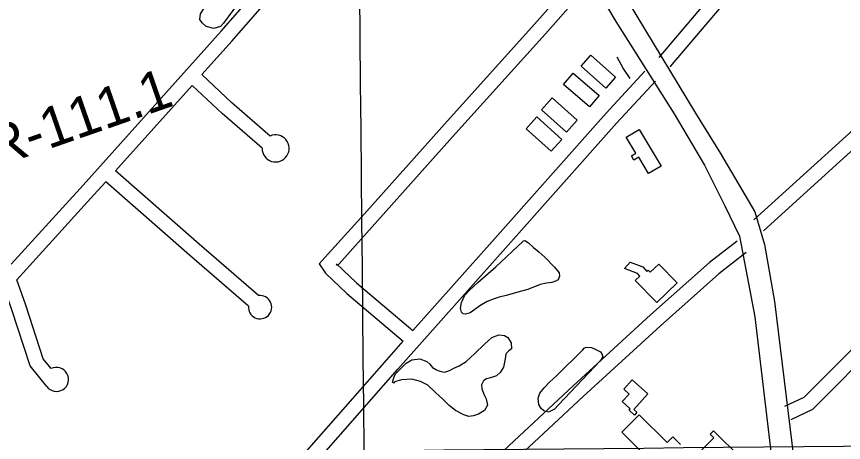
# Model space of a CAD drawing. Extents: x 3625074 to 3663148, y 511451 to 537151.
# Drawn here: x 3633748 to 3635455, y 529050 to 529928 of the extents above; entities that cross this region are included whole.
import ezdxf

# ---------------------------------------------------------------- set-up
doc = ezdxf.new("R2010")
doc.units = 0
for name, color, linetype in [('V-BLDG-OTLN', 7, 'Continuous'), ('V-GRID-MAJR', 7, 'Continuous'), ('V-RIVR-RANG-IDEN', 7, 'Continuous'), ('V-ROAD-CNTR', 7, 'Continuous'), ('V-SITE-VEGE', 7, 'Continuous'), ('V-SURV-IDEN', 7, 'Continuous'), ('V-TOPO-SHOR', 7, 'Continuous')]:
    doc.layers.add(name, color=color, linetype=linetype)

msp = doc.modelspace()

# ---------------------------------------------------------------- linework, layer by layer
at = {"layer": 'V-BLDG-OTLN'}
for points in [[(3634933.9560000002, 529848.573), (3634984.804, 529803.001), (3634964.6780000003, 529780.547), (3634913.83, 529826.1190000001)], [(3634930.827, 529742.05), (3634877.239, 529788.45), (3634897.469, 529811.8150000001), (3634951.057, 529765.416)], [(3634883.665, 529690.047), (3634832.037, 529736.023), (3634853.848, 529760.517), (3634905.4790000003, 529714.542)], [(3634852.022, 529650.398), (3634800.004, 529696.773), (3634821.867, 529721.296), (3634873.88, 529674.917)], [(3635033.1750000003, 529695.335), (3635078.8680000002, 529619.953), (3635053.0470000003, 529604.302), (3635032.532, 529638.143), (3635022.714, 529632.194), (3635017.3910000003, 529640.973), (3635026.5870000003, 529646.5480000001), (3635006.73, 529679.306)], [(3635111.9250000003, 529379.204), (3635070.037, 529338.133), (3635025.504, 529383.554), (3635035.049, 529392.9130000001), (3635030.021, 529398.49), (3635003.037, 529408.716), (3635014.629, 529421.522), (3635041.224, 529411.696), (3635049.348, 529402.531), (3635052.275, 529405.13), (3635055.88, 529401.066), (3635074.4220000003, 529417.455)], [(3634998.632, 529133.907), (3635012.622, 529149.433), (3635001.687, 529159.284), (3635019.12, 529178.629), (3635051.315, 529149.617), (3635022.495, 529117.638), (3635028.9050000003, 529111.862), (3635023.603, 529105.978), (3635012.532, 529115.958), (3635015.227, 529118.954)]]:
    msp.add_lwpolyline(points, close=True, dxfattribs=at)
for points in [[(3635038.562, 529030.131), (3634997.589, 529070.513), (3635033.45, 529106.898), (3635091.572, 529049.613), (3635102.846, 529061.053), (3635118.864, 529045.267)], [(3635135.852, 529006.72), (3635187.5500000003, 529059.1730000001), (3635180.042, 529066.575), (3635186.921, 529073.554), (3635244.406, 529016.8960000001)]]:
    msp.add_lwpolyline(points, dxfattribs=at)
at = {"layer": 'V-GRID-MAJR'}
for points in [[(3634583.656, 516913.037), (3634524.612, 522971.789), (3634465.549, 529032.474), (3634406.486, 535093.172), (3634406.467, 535095.091)], [(3629187.62, 528981.4230000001), (3634465.549, 529032.474), (3639743.471, 529084.2930000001), (3645021.3850000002, 529136.879)]]:
    msp.add_spline(points, degree=3, dxfattribs=at)
at = {"layer": 'V-ROAD-CNTR'}
for points in [[(3633673.938, 532162.153), (3633780.89, 531985.916), (3633876.6, 531828.509), (3633996.825, 531630.389), (3634264.9990000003, 531191.1460000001), (3634381.197, 530998.172), (3634645.052, 530565.506), (3634778.911, 530342.151), (3635026.809, 529932.475), (3635149.623, 529729.158), (3635201.133, 529645.657), (3635237.929, 529583.988), (3635272.433, 529525.164), (3635292.1520000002, 529457.799), (3635312.892, 529340.52), (3635368.435, 528885.332), (3635402.846, 528578.8960000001), (3635468.14, 527984.167), (3635498.877, 527720.385)], [(3633679.897, 532075.356), (3633969.983, 531601.076), (3634194.6240000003, 531230.475), (3634340.754, 530986.403), (3634517.023, 530698.934), (3634735.024, 530339.394), (3634985.259, 529918.023), (3635105.444, 529727.834), (3635168.1010000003, 529621.4130000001), (3635210.481, 529537.829), (3635240.924, 529474.947), (3635272.682, 529308.5700000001), (3635319.328, 528914.598), (3635361.137, 528548.576), (3635414.789, 528072.17), (3635474.574, 527551.515)], [(3633736.983, 529417.275), (3633885.366, 529580.647), (3634170.376, 529898.301), (3634411.054, 530173.101), (3634609.2, 530397.257), (3634634.475, 530427.709), (3634669.275, 530458.221)], [(3634130.2800000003, 529808.691), (3634192.826, 529878.401), (3634433.576, 530153.283), (3634631.986, 530377.737), (3634656.041, 530406.719), (3634676.843, 530424.959)], [(3635097.576, 529824.55), (3635282.205, 530042.104), (3635443.794, 530224.98)], [(3635074.702, 529843.962), (3635259.525, 530061.7440000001), (3635337.7830000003, 530150.311)], [(3634916.355, 530024.9720000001), (3634817.649, 529912.602), (3634625.97, 529700.118), (3634465.501, 529520.884), (3634391.5530000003, 529438.5160000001), (3634372.912, 529418.077), (3634385.518, 529398.6630000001), (3634429.657, 529356.58), (3634546.188, 529258.274)], [(3634938.895, 530005.174), (3634840.057, 529892.654), (3634648.284, 529680.066), (3634487.839, 529500.858), (3634413.799, 529418.388), (3634410.6920000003, 529414.981), (3634408.764, 529417.949), (3634449.699, 529378.922), (3634566.16, 529280.675)], [(3635270.429, 529508.681), (3635585.307, 529794.431), (3635751.312, 529950.38)], [(3635290.589, 529486.465), (3635605.659, 529772.389), (3635739.305, 529897.9400000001)], [(3634566.16, 529280.674), (3634729.704, 529464.107), (3634965.34, 529729.268), (3635045.515, 529815.501)], [(3633810.1350000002, 529165.0700000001), (3633775.994, 529207.667), (3633738.269, 529322.968), (3633699.028, 529434.85), (3633629.878, 529629.93), (3633592.8140000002, 529733.631), (3633587.857, 529753.635), (3633584.154, 529798.039)], [(3634271.469, 529681.875), (3634192.36, 529750.497), (3634130.2800000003, 529808.691)], [(3633912.299, 528497.0650000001), (3634024.046, 528624.74), (3634254.102, 528881.164), (3634534.839, 529200.464), (3634752.112, 529444.161), (3634987.54, 529709.088), (3635067.485, 529795.073)], [(3633951.913, 529609.895), (3634110.24, 529786.356)], [(3634254.813, 529656.609), (3634172.2660000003, 529728.215), (3634110.241, 529786.355)], [(3635334.545, 529124.263), (3635374.307, 529142.9890000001), (3635510.6780000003, 529279.305), (3635826.258, 529611.095), (3635924.861, 529720.085)], [(3635347.327, 529097.123), (3635391.819, 529118.075), (3635532.154, 529258.355), (3635848.254, 529590.691), (3635946.595, 529699.3910000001)], [(3634247.738, 529352.502), (3634124.87, 529458.427), (3633951.914, 529609.895)], [(3633748.273, 529385.085), (3633907.634, 529560.545), (3633931.877, 529587.564)], [(3634226.744, 529330.992), (3634105.1920000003, 529435.781), (3633931.878, 529587.564)], [(3635235.9250000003, 529465.003), (3635178.539, 529420.721), (3635057.132, 529312.661), (3634897.5530000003, 529166.2980000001), (3634754.852, 529033.805), (3634624.396, 528911.731), (3634488.5840000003, 528777.251)], [(3635254.253, 529441.251), (3635197.699, 529397.613), (3635077.244, 529290.401), (3634917.899, 529144.25), (3634775.308, 529011.859), (3634645.204, 528890.115), (3634530.733, 528776.77)], [(3633819.106, 529201.8470000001), (3633802.812, 529222.177), (3633766.683, 529332.598), (3633748.274, 529385.085)], [(3634025.85, 528671.675), (3634231.6720000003, 528901.086), (3634512.377, 529220.35), (3634546.188, 529258.273)]]:
    msp.add_lwpolyline(points, dxfattribs=at)
for centre, radius, start, end in [((3634282.768383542, 529656.3027480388), 27.95717053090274, 179.37302008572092, 113.83899508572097), ((3634250.670490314, 529328.6388426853), 24.042239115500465, 174.38260938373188, 97.0053927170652), ((3633830.337554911, 529179.6248104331), 24.899164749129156, 215.77029654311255, 116.81182432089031)]:
    msp.add_arc(centre, radius, start, end, dxfattribs=at)
at = {"layer": 'V-SITE-VEGE'}
for points in [[(3634142.2770000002, 530096.686), (3634141.742, 530100.202), (3634141.761, 530101.372), (3634143.582, 530106.023), (3634145.953, 530108.327), (3634157.61, 530105.816), (3634225.7490000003, 530047.526), (3634247.077, 530026.751), (3634249.863, 530017.357), (3634175.287, 529914.961), (3634168.756, 529908.041), (3634155.245, 529903.562), (3634139.518, 529907.883), (3634130.861, 529915.61), (3634126.2800000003, 529922.108), (3634127.619, 529933.782), (3634146.176, 529963.328), (3634194.384, 530021.674), (3634203.418, 530039.6680000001), (3634201.792, 530048.46), (3634196.608, 530053.799)], [(3634792.953, 529464.276), (3634794.725, 529465.419), (3634797.6550000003, 529465.961), (3634805.194, 529461.759), (3634814.988, 529451.675), (3634826.549, 529442.737), (3634838.673, 529432.036), (3634858.8310000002, 529411.28), (3634868.012, 529399.453), (3634869.079, 529392.424), (3634866.055, 529385.448), (3634860.75, 529382.604), (3634853.109, 529379.792), (3634841.9760000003, 529378.201), (3634829.076, 529375.464), (3634803.785, 529365.31), (3634790.2830000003, 529361.415), (3634758.59, 529353.108), (3634744.502, 529349.221), (3634733.9280000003, 529345.8690000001), (3634719.815, 529340.227), (3634704.49, 529331.68), (3634693.846, 529323.652), (3634684.393, 529316.775), (3634674.997, 529313.988), (3634670.329, 529314.6410000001), (3634666.876, 529318.198), (3634664.654, 529326.417), (3634666.5870000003, 529338.666), (3634673.239, 529353.77), (3634683.322, 529363.561), (3634700.515, 529379.681), (3634737.231, 529411.886)], [(3634528.552, 529174.64), (3634527.926, 529171.725), (3634523.858, 529173.542), (3634526.299, 529180.519), (3634528.147, 529186.9230000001), (3634531.147, 529192.142), (3634541.829, 529203.095), (3634552.506, 529213.461), (3634564.298, 529220.306), (3634580.69, 529221.821), (3634595.227, 529216.345), (3634600.9960000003, 529211), (3634606.747, 529204.483), (3634614.855, 529199.105), (3634621.835, 529196.664), (3634631.745, 529194.765), (3634638.2, 529196.424), (3634643.494, 529198.685), (3634650.5700000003, 529202.6730000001), (3634661.752, 529207.772), (3634676.504, 529216.912), (3634694.279, 529233.024), (3634713.857, 529252.615), (3634729.258, 529266.4230000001), (3634743.951, 529271.469), (3634755.6240000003, 529270.128), (3634762.579, 529265.935), (3634769.438, 529255.312), (3634769.844, 529243.028), (3634764.517, 529238.431), (3634759.1780000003, 529233.245), (3634757.984, 529231.508), (3634756.679, 529222.174), (3634753.498, 529204.68), (3634746.322, 529193.676), (3634739.214, 529187.349), (3634728.632, 529183.409), (3634718.068, 529180.642), (3634712.758, 529177.212), (3634712.164, 529176.636), (3634707.953, 529168.512), (3634708.418, 529160.3200000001), (3634713.4990000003, 529147.968), (3634717.47, 529139.725), (3634720.2060000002, 529126.823), (3634714.1890000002, 529115.2170000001), (3634701.805, 529107.799), (3634691.231, 529104.444), (3634681.861, 529103.41), (3634671.384, 529106.488), (3634654.558, 529115.504), (3634641.258, 529125.637), (3634627.4280000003, 529139.287), (3634613.577, 529151.765), (3634597.443, 529167.787), (3634581.77, 529175.616), (3634564.294, 529179.964), (3634542.651, 529179.11)], [(3634917.146, 529240.878), (3634920.12, 529244.341), (3634924.238, 529246.037), (3634935.3340000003, 529245.289), (3634942.8910000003, 529242.256), (3634953.328, 529236.258), (3634957.342, 529230.935), (3634958.444, 529226.243), (3634953.656, 529218.713), (3634866.958, 529127.017), (3634858.647, 529118.371), (3634846.2770000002, 529112.118), (3634836.377, 529114.602), (3634831.181, 529119.358), (3634826.622, 529127.607), (3634825.068, 529141.077), (3634828.719, 529150.963), (3634837.065, 529161.948), (3634848.352, 529174.062), (3634863.753, 529187.87)]]:
    msp.add_lwpolyline(points, close=True, dxfattribs=at)
at = {"layer": 'V-TOPO-SHOR'}
msp.add_lwpolyline([(3635015.0810000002, 529800.267), (3635000.622, 529821.75), (3634987.951, 529844.3910000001)], dxfattribs=at)

# ---------------------------------------------------------------- texts
at = {"layer": 'V-RIVR-RANG-IDEN'}
msp.add_text('R-111.1', height=82.999998, rotation=19.180814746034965, dxfattribs=at).set_placement((3633702.9693686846, 529615.8242466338))
at = {"layer": 'V-SURV-IDEN'}
msp.add_text('223+30.4', height=100.00000000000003, rotation=24.05339806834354, dxfattribs=at).set_placement((3633479.8471969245, 529868.598058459))

doc.saveas('drawing.dxf')
